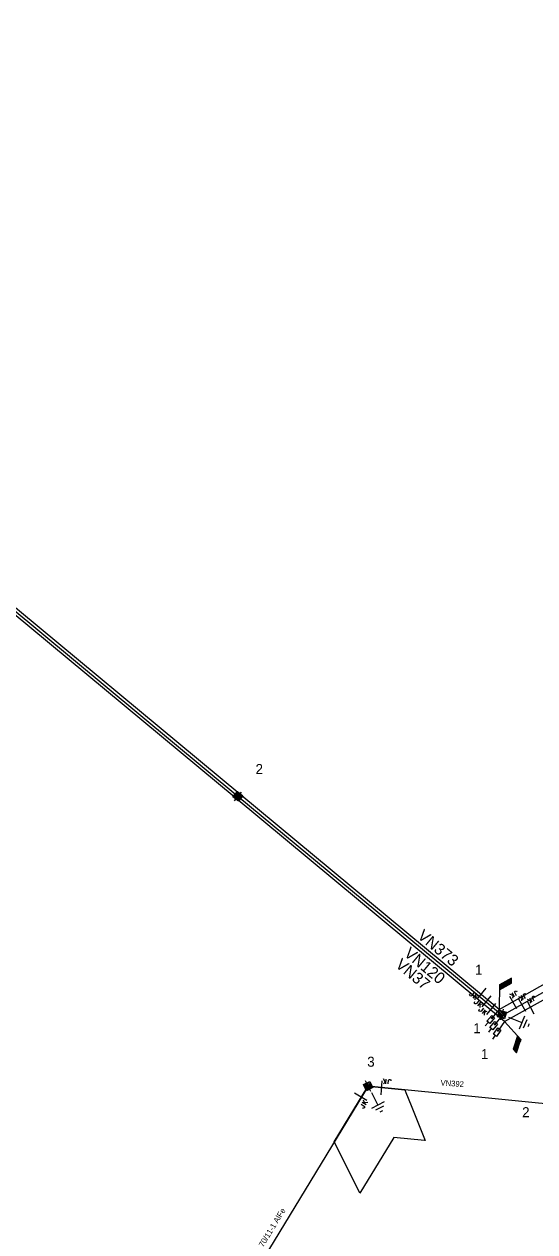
# Model space of a CAD drawing. Extents: x -540879 to -537255, y -1184046 to -1180016.
# Drawn here: x -537632.5 to -537543.2, y -1180686.9 to -1180475.4 of the extents above; entities that cross this region are included whole.
import ezdxf

# ---------------------------------------------------------------- set-up
doc = ezdxf.new("R2010")
doc.units = 0
for name, color, linetype in [('Default', 7, 'Continuous'), ('Vrstva 1', 7, 'Continuous'), ('Vrstva 11', 7, 'Continuous'), ('Vrstva 12', 7, 'Continuous'), ('Vrstva 13', 7, 'Continuous'), ('Vrstva 14', 7, 'Continuous'), ('Vrstva 15', 7, 'Continuous'), ('Vrstva 16', 7, 'Continuous'), ('Vrstva 18', 7, 'Continuous'), ('Vrstva 2', 7, 'Continuous'), ('Vrstva 3', 7, 'Continuous'), ('Vrstva 35', 7, 'Continuous'), ('Vrstva 50', 7, 'Continuous'), ('Vrstva 51', 7, 'Continuous')]:
    doc.layers.add(name, color=color, linetype=linetype)

# ---------------------------------------------------------------- blocks, each defined once
blk = doc.blocks.new('VN840')
at = {"layer": 'Vrstva 15'}
for points in [[(-0.01, 1.41), (-0.01, -1.09)], [(-1.51, -1.24), (-1.51, -1.15)], [(-1.48, -1.35), (-1.51, -1.24)], [(-1.33, -1.42), (-1.48, -1.35)], [(-1.27, -1.42), (-1.33, -1.42)], [(-1.13, -1.35), (-1.27, -1.42)], [(-1.09, -1.24), (-1.13, -1.35)], [(-1.09, -0.59), (-1.09, -1.24)], [(-0.68, -0.59), (-0.68, -1.42)], [(-0.68, -1.11), (-0.27, -0.59)], [(-0.54, -0.94), (-0.2, -1.42)]]:
    blk.add_lwpolyline(points, dxfattribs=at)
blk = doc.blocks.new('VN820')
at = {"layer": 'Vrstva 13'}
for points in [[(0, 0), (0, -2.1)], [(-0.32, -1.63), (0.34, -1.63)], [(-0.32, -2.95), (-0.32, -1.63)], [(0, -2.1), (-0.12, -1.86)], [(0, -2.1), (0.12, -1.86)], [(0.34, -1.63), (0.34, -2.95)], [(0.34, -2.95), (-0.32, -2.95)], [(0, -2.95), (0, -3.75)]]:
    blk.add_lwpolyline(points, dxfattribs=at)
blk = doc.blocks.new('VN810')
at = {"layer": 'Vrstva 14'}
for points in [[(0, -1.25), (0, -3.75)], [(1.25, -3.75), (-1.25, -3.75)], [(0.77, -4.37), (-0.8, -4.37)], [(0, -5), (-0.25, -5)], [(0.27, -5), (0, -5)]]:
    blk.add_lwpolyline(points, dxfattribs=at)
blk = doc.blocks.new('VN001')
at = {"layer": 'Default'}
for p, q in [((1.73, 3.03), (4.14, 3.03)), ((1.76, 3.08), (4.17, 3.08)), ((1.79, 3.13), (4.2, 3.13)), ((1.82, 3.18), (4.23, 3.18)), ((1.85, 3.23), (4.26, 3.23)), ((1.87, 3.28), (4.29, 3.28)), ((1.9, 3.33), (4.32, 3.33)), ((1.93, 3.38), (4.35, 3.38)), ((1.96, 3.43), (4.37, 3.43)), ((1.99, 3.48), (4.4, 3.48)), ((2.02, 3.53), (4.43, 3.53)), ((2.05, 3.58), (4.46, 3.58)), ((2.07, 3.63), (4.49, 3.63)), ((2.1, 3.68), (4.52, 3.68)), ((2.13, 3.73), (2.54, 3.73))]:
    blk.add_line(p, q, dxfattribs=at)
blk.add_lwpolyline([(2.13, 3.73), (0, 0)], dxfattribs=at)
blk.add_lwpolyline([(4.55, 3.73), (2.13, 3.73), (1.7, 2.98), (4.12, 2.99)], close=True, dxfattribs=at)
blk = doc.blocks.new('VN470')
at = {"layer": 'Vrstva 2'}
for points in [[(-1.23, 1.22), (1.23, 1.22)], [(-1.23, -1.23), (-1.23, 1.22)], [(-0.92, 0.9), (0.92, 0.9)], [(-0.92, -0.95), (-0.92, 0.9)], [(-0.61, 0.61), (0.61, 0.61)], [(-0.61, -0.62), (-0.61, 0.61)], [(-0.31, -0.27), (-0.31, 0.34)], [(-0.31, 0.34), (0.31, 0.34)], [(0, 1.22), (0, 1.97)], [(0.31, 0.34), (0.31, -0.27)], [(0.61, 0.61), (0.61, -0.62)], [(0.92, 0.9), (0.92, -0.95)], [(1.23, 1.22), (1.23, -1.23)], [(1.23, -1.23), (-1.23, -1.23)], [(0.92, -0.95), (-0.92, -0.95)], [(0.61, -0.62), (-0.61, -0.62)], [(0.31, -0.27), (-0.31, -0.27)], [(0, -1.23), (0, -1.98)]]:
    blk.add_lwpolyline(points, dxfattribs=at)

msp = doc.modelspace()

# ---------------------------------------------------------------- linework, layer by layer
at = {"layer": 'Vrstva 1'}
for points in [[(-537549.42, -1180647.98), (-537524.99, -1180634.15)], [(-537548.92, -1180649.04), (-537524.29, -1180635.07)], [(-537548.49, -1180650.05), (-537523.4, -1180636.11)], [(-537531.99, -1180665.41), (-537572.36, -1180661.38), (-537627.26, -1180751.9)]]:
    msp.add_lwpolyline(points, dxfattribs=at)
at = {"layer": 'Vrstva 35'}
msp.add_lwpolyline([(-537565.92, -1180662.02), (-537565.73, -1180662.5), (-537564.81, -1180664.81), (-537562.5, -1180670.63), (-537562.39, -1180670.91), (-537562.5, -1180670.9), (-537567.87, -1180670.37), (-537573.79, -1180680.13), (-537575.9, -1180675.9), (-537578.28, -1180671.14), (-537573.04, -1180662.5), (-537572.36, -1180661.38)], close=True, dxfattribs=at)
at = {"layer": 'Vrstva 50'}
for points in [[(-537549.42, -1180647.98), (-537594.82, -1180610.26), (-537640.66, -1180572.18), (-537698.89, -1180545.49), (-537770.12, -1180529.84), (-537817.09, -1180530.41), (-537899.91, -1180516.71), (-537967.43, -1180502.43), (-538028.9, -1180486.5), (-538083.27, -1180475.39)], [(-537548.92, -1180649.05), (-537595.14, -1180610.65), (-537640.93, -1180572.61), (-537699.05, -1180545.96), (-537770.17, -1180530.35), (-537817.13, -1180530.91), (-537900, -1180517.2), (-537967.54, -1180502.92), (-538029.01, -1180486.99), (-538083.27, -1180475.98)], [(-537548.49, -1180650.05), (-537595.46, -1180611.03), (-537641.2, -1180573.04), (-537699.21, -1180546.44), (-537770.22, -1180530.85), (-537817.17, -1180531.41), (-537900.09, -1180517.69), (-537967.65, -1180503.41), (-538029.12, -1180487.48), (-538083.26, -1180476.62)]]:
    msp.add_lwpolyline(points, dxfattribs=at)

# ---------------------------------------------------------------- block references
at = {"layer": 'Vrstva 11'}
for p, rotation in [((-537549.42, -1180647.98), 29.01520601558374), ((-537548.49, -1180650.05), -108.56155173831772)]:
    msp.add_blockref('VN001', p, dxfattribs=dict(at, rotation=rotation))
at = {"layer": 'Vrstva 13', "yscale": 0.5000000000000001}
for p, xscale, rotation in [((-537595.14, -1180610.65), 0.5, -39.71826941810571), ((-537548.93, -1180648.84), 0.5, -16.91475459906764), ((-537572.36, -1180661.38), 0.49999999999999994, 26.600749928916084)]:
    msp.add_blockref('VN470', p, dxfattribs=dict(at, xscale=xscale, rotation=rotation))
at = {"layer": 'Vrstva 15'}
for p, rotation in [((-537548.93, -1180648.84), 67.42777229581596), ((-537572.36, -1180661.38), 27.089867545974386)]:
    msp.add_blockref('VN810', p, dxfattribs=dict(at, rotation=rotation))
at = {"layer": 'Vrstva 16'}
for p, rotation in [((-537549.42, -1180647.98), -40.379696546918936), ((-537548.92, -1180649.05), -39.7186694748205), ((-537548.49, -1180650.05), -34.27847861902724)]:
    msp.add_blockref('VN820', p, dxfattribs=dict(at, rotation=rotation))
at = {"layer": 'Vrstva 18'}
for p, rotation in [((-537552.63, -1180645.31), -39.71819569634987), ((-537551.77, -1180646.68), -39.71864653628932), ((-537550.96, -1180648), -39.718461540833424), ((-537547.04, -1180646.63), -150.4898988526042), ((-537545.48, -1180647.1), -150.4369978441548), ((-537543.97, -1180647.54), -150.94920141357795), ((-537569.96, -1180661.54), 176.1224721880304), ((-537573.53, -1180663.31), 58.7630000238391)]:
    msp.add_blockref('VN840', p, dxfattribs=dict(at, rotation=rotation))

# ---------------------------------------------------------------- texts
at = {"layer": 'Vrstva 12'}
for s, p in [('1', (-537553.65, -1180641.9)), ('1', (-537552.62, -1180656.67)), ('2', (-537545.41, -1180666.84))]:
    msp.add_text(s, height=1.75, dxfattribs=at).set_placement(p)
at = {"layer": 'Vrstva 14'}
for s, p in [('2', (-537592.05, -1180606.73)), ('1', (-537553.96, -1180652.13)), ('3', (-537572.51, -1180658))]:
    msp.add_text(s, height=1.75, dxfattribs=at).set_placement(p)
at = {"layer": 'Vrstva 2'}
msp.add_text('70/11-1 AlFe', height=1, rotation=58.763, dxfattribs=at).set_placement((-537590.71, -1180689.69))
at = {"layer": 'Vrstva 3'}
msp.add_text('VN392', height=1, rotation=356.122, dxfattribs=at).set_placement((-537559.71, -1180661.29))
at = {"layer": 'Vrstva 51'}
for s, p in [('VN373', (-537563.87, -1180635.33)), ('VN120', (-537566.22, -1180638.44)), ('VN37', (-537567.72, -1180640.4))]:
    msp.add_text(s, height=2, rotation=320.281, dxfattribs=at).set_placement(p)

doc.saveas('drawing.dxf')
